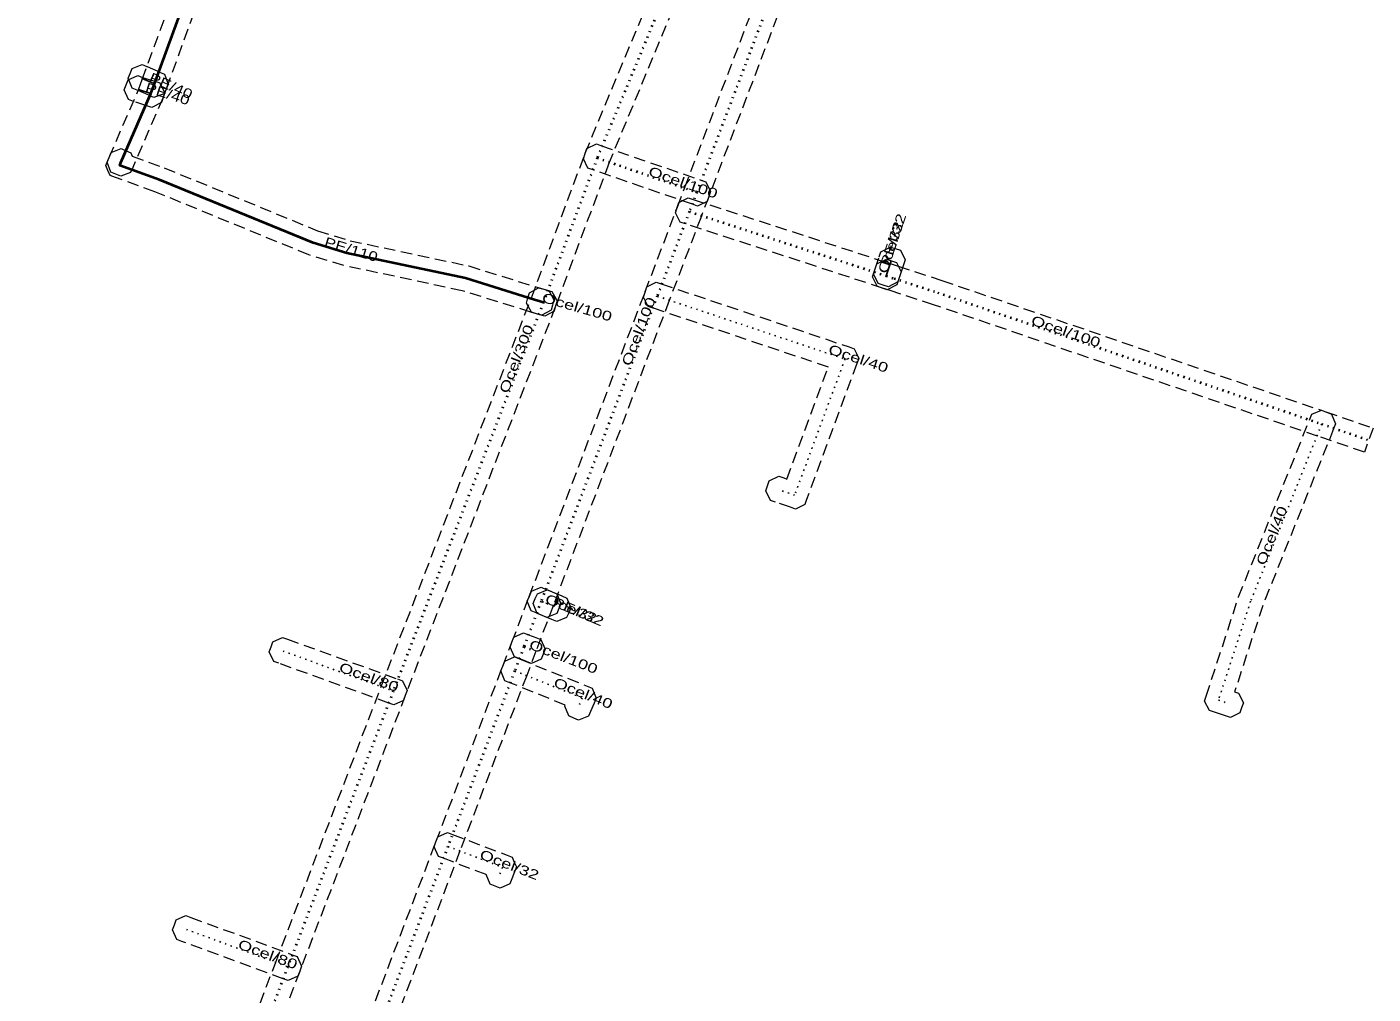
# Model space of a CAD drawing. Extents: x -644301 to -644150, y -1042432 to -1042139.
# Drawn here: x -644293.9 to -644188.9, y -1042360.2 to -1042284.7 of the extents above; entities that cross this region are included whole.
import ezdxf

# ---------------------------------------------------------------- set-up
doc = ezdxf.new("R2010")
doc.units = 0
doc.header["$LTSCALE"] = 0.3
doc.linetypes.add('DOTTED', pattern=[1.5, 0.3, -1.2])
doc.linetypes.add('MEDIUM_DASHED', pattern=[4.5, 3, -1.5])
for name, color, linetype, lineweight in [('1', 7, 'MEDIUM_DASHED', 13), ('14', 7, 'Continuous', 25), ('18', 7, 'DOTTED', 25)]:
    doc.layers.add(name, color=color, linetype=linetype, lineweight=lineweight)
doc.layers.add('20', color=7, linetype='Continuous')

msp = doc.modelspace()

# ---------------------------------------------------------------- linework, layer by layer
at = {"layer": '1'}
for points in [[(-644270.272, -1042254.427), (-644283.063, -1042289.46), (-644283.349, -1042290.248), (-644285.69, -1042295.655), (-644285.855, -1042296.035), (-644286.625, -1042296.34), (-644287.005, -1042296.176), (-644287.385, -1042296.011), (-644287.69, -1042295.241), (-644287.526, -1042294.861), (-644285.209, -1042289.51), (-644284.943, -1042288.776), (-644272.15, -1042253.741)], [(-644237.888, -1042269.645), (-644248.531, -1042295.264), (-644252.728, -1042306.532), (-644264.437, -1042336.864), (-644272.664, -1042358.382), (-644284.912, -1042390.417), (-644285.773, -1042395.45), (-644288.212, -1042409.691), (-644291.99, -1042431.748), (-644293.942, -1042431.295), (-644290.184, -1042409.353), (-644287.745, -1042395.112), (-644286.85, -1042389.887), (-644274.532, -1042357.668), (-644266.303, -1042336.146), (-644254.598, -1042305.822), (-644250.393, -1042294.532), (-644239.756, -1042268.927)], [(-644267.232, -1042361.936), (-644262.038, -1042348.274), (-644256.831, -1042334.576), (-644256.114, -1042332.69), (-644254.764, -1042329.138), (-644245.715, -1042305.332), (-644243.209, -1042298.74), (-644242.633, -1042297.224), (-644233.926, -1042274.319)], [(-644232.058, -1042275.033), (-644240.763, -1042297.934), (-644241.339, -1042299.45), (-644243.845, -1042306.042), (-644252.894, -1042329.848), (-644254.244, -1042333.4), (-644254.961, -1042335.286), (-644260.168, -1042348.984), (-644265.362, -1042362.646)]]:
    msp.add_lwpolyline(points, dxfattribs=at)
for points in [[(-644284.96, -1042287.61), (-644284.578, -1042287.771), (-644284.551, -1042287.783), (-644283.626, -1042288.191), (-644283.594, -1042288.205), (-644283.216, -1042288.375), (-644282.921, -1042289.149), (-644283.09, -1042289.527), (-644283.26, -1042289.905), (-644284.034, -1042290.2), (-644284.412, -1042290.031), (-644284.438, -1042290.019), (-644285.343, -1042289.619), (-644285.354, -1042289.615), (-644285.736, -1042289.454), (-644286.049, -1042288.687), (-644285.888, -1042288.305), (-644285.727, -1042287.923)], [(-644285.301, -1042288.48), (-644284.932, -1042288.62), (-644283.975, -1042288.926), (-644283.58, -1042289.052), (-644283.2, -1042289.789), (-644283.326, -1042290.183), (-644283.452, -1042290.578), (-644284.189, -1042290.958), (-644284.583, -1042290.832), (-644285.579, -1042290.513), (-644285.626, -1042290.495), (-644286.013, -1042290.348), (-644286.351, -1042289.592), (-644286.204, -1042289.205), (-644286.057, -1042288.818)], [(-644249.527, -1042293.818), (-644249.136, -1042293.953), (-644241.372, -1042296.634), (-644240.98, -1042296.769), (-644240.618, -1042297.514), (-644240.753, -1042297.905), (-644240.888, -1042298.297), (-644241.633, -1042298.659), (-644242.024, -1042298.524), (-644249.788, -1042295.843), (-644250.18, -1042295.708), (-644250.542, -1042294.963), (-644250.407, -1042294.572), (-644250.272, -1042294.18)], [(-644285.832, -1042294.503), (-644285.721, -1042294.78), (-644283.247, -1042295.673), (-644271.273, -1042300.586), (-644268.731, -1042301.364), (-644259.484, -1042303.333), (-644254.067, -1042305.019), (-644253.628, -1042305.147), (-644253.23, -1042305.262), (-644252.831, -1042305.988), (-644252.947, -1042306.386), (-644253.062, -1042306.784), (-644253.788, -1042307.183), (-644254.186, -1042307.067), (-644254.643, -1042306.935), (-644259.99, -1042305.269), (-644269.233, -1042303.302), (-644271.947, -1042302.472), (-644283.967, -1042297.539), (-644287.046, -1042296.429), (-644287.453, -1042296.282), (-644287.624, -1042295.886), (-644287.796, -1042295.489), (-644287.626, -1042295.093), (-644287.527, -1042294.863), (-644287.363, -1042294.482), (-644286.593, -1042294.175), (-644286.213, -1042294.339)], [(-644188.944, -1042315.981), (-644189.622, -1042317.863), (-644193.271, -1042316.614), (-644223.22, -1042306.362), (-644226.608, -1042305.258), (-644227.22, -1042305.058), (-644242.584, -1042300.046), (-644242.978, -1042299.918), (-644243.353, -1042299.179), (-644243.225, -1042298.785), (-644243.097, -1042298.391), (-644242.358, -1042298.016), (-644241.964, -1042298.144), (-644226.6, -1042303.156), (-644225.988, -1042303.356), (-644222.586, -1042304.466), (-644192.623, -1042314.722)], [(-644227.911, -1042303.953), (-644227.781, -1042303.559), (-644227.471, -1042302.621), (-644227.341, -1042302.228), (-644226.602, -1042301.856), (-644226.208, -1042301.986), (-644225.815, -1042302.116), (-644225.443, -1042302.855), (-644225.573, -1042303.249), (-644225.883, -1042304.187), (-644226.013, -1042304.58), (-644226.752, -1042304.952), (-644227.146, -1042304.822), (-644227.539, -1042304.692)], [(-644227.99, -1042304.184), (-644227.859, -1042303.791), (-644227.781, -1042303.557), (-644227.65, -1042303.164), (-644226.909, -1042302.793), (-644226.516, -1042302.924), (-644226.123, -1042303.055), (-644225.752, -1042303.796), (-644225.883, -1042304.189), (-644225.961, -1042304.423), (-644226.092, -1042304.816), (-644226.833, -1042305.187), (-644227.226, -1042305.056), (-644227.619, -1042304.925)], [(-644244.855, -1042304.607), (-644244.462, -1042304.739), (-644229.818, -1042309.655), (-644229.417, -1042309.79), (-644229.234, -1042310.171), (-644229.051, -1042310.553), (-644229.198, -1042310.95), (-644233.124, -1042321.572), (-644233.265, -1042321.954), (-644234.001, -1042322.303), (-644234.386, -1042322.171), (-644235.559, -1042321.769), (-644235.951, -1042321.635), (-644236.315, -1042320.891), (-644236.181, -1042320.499), (-644236.047, -1042320.107), (-644235.303, -1042319.743), (-644234.911, -1042319.877), (-644234.661, -1042319.962), (-644231.431, -1042311.223), (-644245.098, -1042306.635), (-644245.491, -1042306.503), (-644245.86, -1042305.762), (-644245.728, -1042305.369), (-644245.596, -1042304.976)], [(-644253.541, -1042307.252), (-644253.939, -1042307.138), (-644254.183, -1042307.068), (-644254.581, -1042306.954), (-644254.982, -1042306.229), (-644254.868, -1042305.831), (-644254.754, -1042305.433), (-644254.029, -1042305.032), (-644253.631, -1042305.146), (-644253.387, -1042305.216), (-644252.989, -1042305.33), (-644252.588, -1042306.055), (-644252.702, -1042306.453), (-644252.816, -1042306.851)], [(-644197.554, -1042329.842), (-644199.745, -1042336.58), (-644199.431, -1042336.686), (-644199.063, -1042337.428), (-644199.196, -1042337.821), (-644199.328, -1042338.213), (-644200.07, -1042338.581), (-644200.463, -1042338.448), (-644201.322, -1042338.158), (-644201.711, -1042338.027), (-644202.08, -1042337.293), (-644201.953, -1042336.902), (-644199.436, -1042329.16), (-644193.875, -1042315.296), (-644193.721, -1042314.912), (-644192.959, -1042314.586), (-644192.575, -1042314.74), (-644192.191, -1042314.894), (-644191.865, -1042315.656), (-644192.019, -1042316.04)], [(-644253.377, -1042330.771), (-644253.758, -1042330.609), (-644254.044, -1042330.488), (-644254.218, -1042330.414), (-644254.6, -1042330.253), (-644254.912, -1042329.485), (-644254.75, -1042329.104), (-644254.589, -1042328.722), (-644253.821, -1042328.41), (-644253.44, -1042328.572), (-644253.264, -1042328.646), (-644252.978, -1042328.767), (-644252.597, -1042328.929), (-644252.285, -1042329.697), (-644252.447, -1042330.078), (-644252.609, -1042330.459)], [(-644253.361, -1042328.606), (-644252.979, -1042328.767), (-644252.218, -1042329.088), (-644251.837, -1042329.249), (-644251.525, -1042330.016), (-644251.686, -1042330.398), (-644251.847, -1042330.779), (-644252.614, -1042331.091), (-644252.996, -1042330.93), (-644253.757, -1042330.609), (-644254.138, -1042330.448), (-644254.45, -1042329.681), (-644254.289, -1042329.299), (-644254.128, -1042328.918)], [(-644274.013, -1042332.319), (-644273.623, -1042332.46), (-644265.03, -1042335.565), (-644264.641, -1042335.705), (-644264.289, -1042336.455), (-644264.43, -1042336.845), (-644264.57, -1042337.234), (-644265.32, -1042337.586), (-644265.71, -1042337.445), (-644274.303, -1042334.34), (-644274.692, -1042334.2), (-644275.044, -1042333.45), (-644274.903, -1042333.06), (-644274.763, -1042332.671)], [(-644255.206, -1042331.963), (-644254.82, -1042332.112), (-644254.248, -1042332.332), (-644253.862, -1042332.481), (-644253.525, -1042333.238), (-644253.674, -1042333.624), (-644253.823, -1042334.01), (-644254.58, -1042334.347), (-644254.966, -1042334.198), (-644255.538, -1042333.978), (-644255.924, -1042333.829), (-644256.261, -1042333.072), (-644256.112, -1042332.686), (-644255.963, -1042332.3)], [(-644251.98, -1042337.676), (-644251.947, -1042337.6), (-644256.27, -1042335.859), (-644256.654, -1042335.704), (-644256.979, -1042334.941), (-644256.824, -1042334.557), (-644256.669, -1042334.173), (-644255.906, -1042333.848), (-644255.522, -1042334.003), (-644250.247, -1042336.127), (-644249.856, -1042336.285), (-644249.696, -1042336.675), (-644249.536, -1042337.066), (-644249.703, -1042337.453), (-644249.98, -1042338.092), (-644250.145, -1042338.472), (-644250.916, -1042338.776), (-644251.296, -1042338.612), (-644251.676, -1042338.447)], [(-644257.798, -1042351.591), (-644258.134, -1042350.837), (-644261.461, -1042349.563), (-644261.847, -1042349.415), (-644262.185, -1042348.658), (-644262.037, -1042348.271), (-644261.889, -1042347.885), (-644261.132, -1042347.547), (-644260.745, -1042347.695), (-644256.486, -1042349.326), (-644256.099, -1042349.474), (-644255.931, -1042349.853), (-644255.762, -1042350.231), (-644255.91, -1042350.618), (-644256.119, -1042351.163), (-644256.267, -1042351.55), (-644257.024, -1042351.887), (-644257.411, -1042351.739)], [(-644281.549, -1042354.027), (-644281.16, -1042354.17), (-644273.252, -1042357.087), (-644272.863, -1042357.23), (-644272.517, -1042357.982), (-644272.66, -1042358.371), (-644272.803, -1042358.76), (-644273.555, -1042359.106), (-644273.944, -1042358.963), (-644281.852, -1042356.046), (-644282.241, -1042355.903), (-644282.587, -1042355.151), (-644282.444, -1042354.762), (-644282.301, -1042354.373)]]:
    msp.add_lwpolyline(points, close=True, dxfattribs=at)
at = {"layer": '14', "lineweight": 40}
msp.add_line((-644253.663, -1042306.177), (-644253.907, -1042306.107), dxfattribs=at)
for points in [[(-644286.608, -1042295.258), (-644284.279, -1042289.879), (-644284.003, -1042289.118), (-644271.211, -1042254.084), (-644270.913, -1042253.269), (-644270.515, -1042252.179), (-644265.386, -1042238.108), (-644265.014, -1042237.088)], [(-644253.907, -1042306.107), (-644254.355, -1042305.977), (-644259.737, -1042304.301), (-644268.982, -1042302.333), (-644271.61, -1042301.529), (-644283.607, -1042296.606), (-644286.707, -1042295.488), (-644286.608, -1042295.258)]]:
    msp.add_lwpolyline(points, dxfattribs=at)
at = {"layer": '14'}
for points in [[(-644284.966, -1042288.693), (-644284.947, -1042288.701), (-644284.032, -1042289.105), (-644284.003, -1042289.118)], [(-644284.279, -1042289.879), (-644285.249, -1042289.569), (-644285.27, -1042289.561)], [(-644226.91, -1042304.107), (-644226.832, -1042303.873), (-644226.522, -1042302.935)]]:
    msp.add_lwpolyline(points, dxfattribs=at)
at = {"layer": '18', "lineweight": 40}
for p, q in [((-644249.462, -1042294.898), (-644241.698, -1042297.579)), ((-644255.179, -1042333.045), (-644254.607, -1042333.265))]:
    msp.add_line(p, q, dxfattribs=at)
at = {"layer": '18'}
for p, q in [((-644253.368, -1042329.688), (-644252.607, -1042330.009)), ((-644273.963, -1042333.4), (-644265.37, -1042336.505)), ((-644281.506, -1042355.108), (-644273.598, -1042358.025))]:
    msp.add_line(p, q, dxfattribs=at)
at = {"layer": '18', "lineweight": 40}
for points in [[(-644214.767, -1042197.36), (-644213.51, -1042198.468), (-644221.219, -1042219.86), (-644227.935, -1042238.495), (-644228.551, -1042240.204), (-644235.868, -1042260.921), (-644238.822, -1042269.286), (-644249.462, -1042294.898), (-644253.663, -1042306.177), (-644265.37, -1042336.505), (-644273.598, -1042358.025), (-644285.881, -1042390.152), (-644286.759, -1042395.281), (-644289.198, -1042409.522), (-644292.966, -1042431.522)], [(-644212.717, -1042220.969), (-644219.305, -1042239.03), (-644219.946, -1042240.7), (-644222.743, -1042247.984), (-644229.688, -1042266.072), (-644232.379, -1042273.081), (-644232.992, -1042274.676), (-644241.698, -1042297.579), (-644242.274, -1042299.095), (-644244.78, -1042305.687), (-644253.829, -1042329.493), (-644255.179, -1042333.045), (-644255.896, -1042334.931), (-644261.103, -1042348.629), (-644266.297, -1042362.291), (-644266.916, -1042363.921), (-644275.457, -1042385.718), (-644275.954, -1042387.015), (-644280.117, -1042397.883), (-644281.39, -1042401.206)], [(-644242.274, -1042299.095), (-644226.91, -1042304.107), (-644226.298, -1042304.307), (-644222.903, -1042305.414), (-644192.947, -1042315.668), (-644189.283, -1042316.922)]]:
    msp.add_lwpolyline(points, dxfattribs=at)
at = {"layer": '18'}
for points in [[(-644244.78, -1042305.687), (-644230.136, -1042310.603), (-644234.062, -1042321.225), (-644235.235, -1042320.823)], [(-644192.947, -1042315.668), (-644198.495, -1042329.501), (-644201.002, -1042337.211), (-644200.143, -1042337.501)], [(-644253.368, -1042329.688), (-644253.654, -1042329.567), (-644253.829, -1042329.493)], [(-644255.896, -1042334.931), (-644250.621, -1042337.055), (-644250.898, -1042337.694)], [(-644261.103, -1042348.629), (-644256.844, -1042350.26), (-644257.053, -1042350.805)]]:
    msp.add_lwpolyline(points, dxfattribs=at)

# ---------------------------------------------------------------- texts
at = {"layer": '20'}
for s, rotation, width, p in [('PE/40', 336.177, 1.3, (-644284.484, -1042288.905)), ('PE/40', 342.277, 1.3, (-644284.775, -1042289.72)), ('Ocel/100', 340.95, 1.4, (-644245.533, -1042296.255)), ('Ocel/32', 71.565, 1.4, (-644226.871, -1042303.99)), ('PE/32', 71.712, 1.3, (-644226.677, -1042303.404)), ('PE/110', 342.989, 1.3, (-644270.802, -1042301.776)), ('Ocel/100', 343.993, 1.4, (-644253.833, -1042306.128)), ('Ocel/100', 69.187, 1.4, (-644246.879, -1042311.207)), ('Ocel/100', 341.104, 1.4, (-644215.684, -1042307.885)), ('Ocel/300', 68.893, 1.4, (-644256.43, -1042313.343)), ('Ocel/40', 341.443, 1.4, (-644231.502, -1042310.144)), ('Ocel/40', 68.146, 1.4, (-644197.399, -1042326.767)), ('Ocel/32', 337.068, 1.4, (-644253.598, -1042329.59)), ('PE/32', 337.129, 1.3, (-644252.987, -1042329.848)), ('Ocel/100', 338.962, 1.4, (-644254.846, -1042333.173)), ('Ocel/80', 340.133, 1.4, (-644269.666, -1042334.952)), ('Ocel/40', 338.068, 1.4, (-644252.935, -1042336.123)), ('Ocel/32', 339.045, 1.4, (-644258.701, -1042349.549)), ('Ocel/80', 339.753, 1.4, (-644277.552, -1042356.566))]:
    msp.add_text(s, height=0.75, rotation=rotation, dxfattribs=dict(at, width=width)).set_placement(p)

doc.saveas('drawing.dxf')
